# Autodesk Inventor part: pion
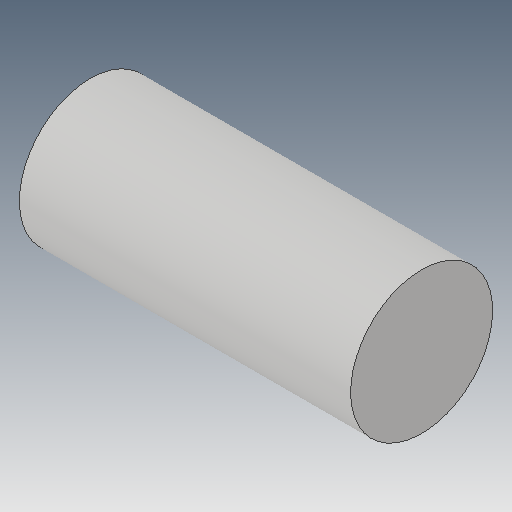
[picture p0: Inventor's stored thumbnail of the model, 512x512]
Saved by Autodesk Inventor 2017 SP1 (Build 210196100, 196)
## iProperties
Created: 2015-12
Part Number: pion
Material: Générique
Document SubType Name: Modeling
Designer: Papa
Density: 1 g/cm^3
Appearance: Par défaut
Author: Papa
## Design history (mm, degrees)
sketch "Esquisse1"
  geometry: C1 r 1.5 at (0, 0); 1 further point
  constraints: 1 centre point, 1 coincident
  dimensions: "d0" = 3 diameter of C1
extrude "Extrusion1" new body sketch "Esquisse1" distance "d1" = 7; taper "d2" = 0 deg
node "Solide1"
